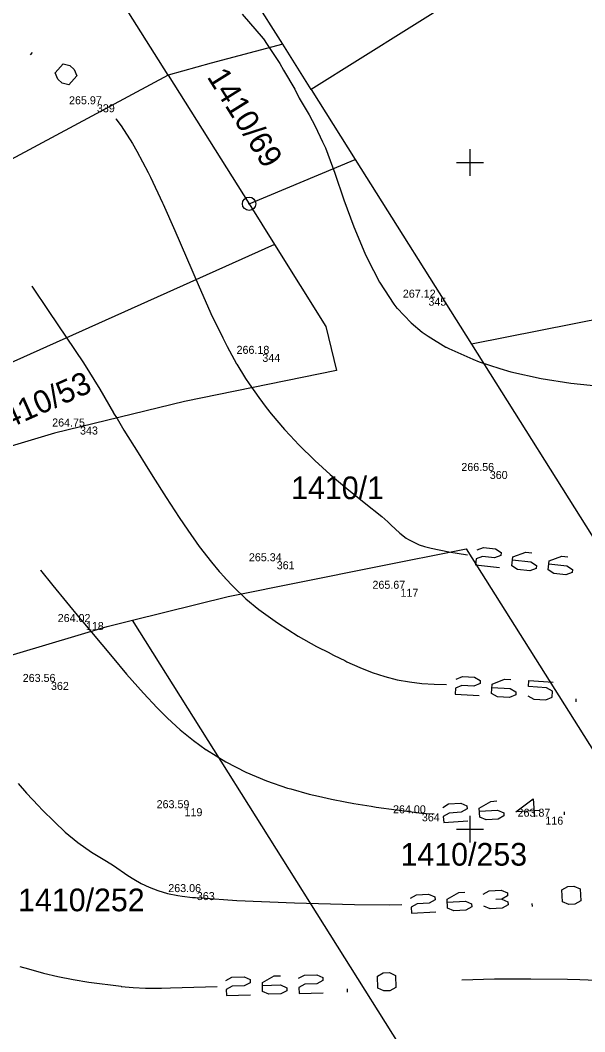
# Model space of a CAD drawing. Extents: x -771260 to -770828, y -1053564 to -1052811.
# Drawn here: x -771133.7 to -771091.4, y -1053315.2 to -1053239.3 of the extents above; entities that cross this region are included whole.
import ezdxf

# ---------------------------------------------------------------- set-up
doc = ezdxf.new("R2010")
doc.units = 0
for name, color, linetype in [('14_8_2023_krizky', 7, 'Continuous'), ('25_3_2019_krizky_JTSK', 7, 'Continuous'), ('25_3_2019_vrstevnice_interval_po_1m', 7, 'Continuous'), ('25_3_2019_zamereny_bod', 7, 'Continuous'), ('25_3_2019_zamereny_bod_cislo', 7, 'Continuous'), ('25_3_2019_zamereny_bod_vyska', 7, 'Continuous'), ('Default', 7, 'Continuous'), ('DKM_Hranice parcel', 7, 'Continuous'), ('DKM_Parcelní čísla', 7, 'Continuous'), ('DKM_Značky bodu BP', 7, 'Continuous')]:
    doc.layers.add(name, color=color, linetype=linetype)

# ---------------------------------------------------------------- blocks, each defined once
blk = doc.blocks.new('POINT_DISPLAY')
at = {"layer": 'Default'}
blk.add_line((0, 0), (0, 0), dxfattribs=at)
blk = doc.blocks.new('KRIZEK')
at = {"layer": '25_3_2019_krizky_JTSK'}
for p, q in [((0, 10), (0, -10)), ((-10, 0), (10, 0))]:
    blk.add_line(p, q, dxfattribs=at)

msp = doc.modelspace()

# ---------------------------------------------------------------- linework, layer by layer
at = {"layer": '25_3_2019_vrstevnice_interval_po_1m'}
for points in [[(-771117.062, -1053238.874), (-771115.486, -1053240.713), (-771115.476, -1053240.728), (-771115.202, -1053241.154), (-771114.241, -1053242.582), (-771113.974, -1053243.076), (-771113.128, -1053244.503), (-771112.786, -1053245.17), (-771112.042, -1053246.435), (-771111.601, -1053247.274), (-771111.043, -1053248.45), (-771110.833, -1053248.912), (-771110.128, -1053250.816), (-771109.441, -1053252.803), (-771108.706, -1053254.837), (-771108.009, -1053256.517), (-771107.828, -1053256.932), (-771107.232, -1053258.116), (-771106.779, -1053258.969), (-771106.417, -1053259.545), (-771105.696, -1053260.633), (-771105.482, -1053260.923), (-771105.468, -1053260.938), (-771104.417, -1053262.017), (-771103.584, -1053262.719), (-771103.128, -1053263.036), (-771101.802, -1053263.855), (-771101.785, -1053263.865), (-771101.586, -1053263.962), (-771099.799, -1053264.752), (-771099.303, -1053264.957), (-771097.772, -1053265.449), (-771096.944, -1053265.702), (-771094.669, -1053266.208), (-771092.454, -1053266.546), (-771090.278, -1053266.772)], [(-771115.486, -1053240.713), (-771115.486, -1053240.713)], [(-771132.92, -1053241.936), (-771132.769, -1053241.767)], [(-771115.202, -1053241.154), (-771115.202, -1053241.154)], [(-771130.888, -1053243.749), (-771131.076, -1053243.278), (-771130.471, -1053242.6), (-771129.982, -1053242.733), (-771129.643, -1053243.035), (-771129.455, -1053243.507), (-771130.06, -1053244.184), (-771130.549, -1053244.051), (-771130.888, -1053243.749)], [(-771114.241, -1053242.582), (-771114.241, -1053242.582)], [(-771113.974, -1053243.076), (-771113.974, -1053243.076)], [(-771113.128, -1053244.503), (-771113.128, -1053244.503)], [(-771112.786, -1053245.17), (-771112.786, -1053245.17)], [(-771126.53, -1053246.725), (-771126.53, -1053246.725)], [(-771126.53, -1053246.725), (-771126.142, -1053247.267), (-771125.29, -1053248.593), (-771124.963, -1053249.162), (-771124.116, -1053250.747), (-771123.933, -1053251.116), (-771123.036, -1053253.033), (-771122.996, -1053253.122), (-771122.104, -1053255.117), (-771120.368, -1053259.156), (-771119.406, -1053261.324), (-771118.528, -1053263.153), (-771118.198, -1053263.802), (-771117.489, -1053265.105), (-771117.48, -1053265.12), (-771116.825, -1053266.205), (-771116.55, -1053266.609), (-771115.825, -1053267.637), (-771115.277, -1053268.378), (-771115.27, -1053268.388), (-771114.893, -1053268.855), (-771113.891, -1053270.031), (-771113.482, -1053270.484), (-771112.819, -1053271.177), (-771111.623, -1053272.355), (-771110.484, -1053273.389), (-771109.231, -1053274.458), (-771107.937, -1053275.51), (-771106.608, -1053276.547), (-771106.593, -1053276.56), (-771106.147, -1053276.951), (-771105.928, -1053277.183), (-771105.269, -1053277.804), (-771104.774, -1053278.168), (-771104.596, -1053278.286), (-771104.161, -1053278.508), (-771103.804, -1053278.67), (-771103.417, -1053278.792), (-771102.92, -1053278.934), (-771102.91, -1053278.936), (-771101.575, -1053279.2), (-771100.189, -1053279.428)], [(-771112.042, -1053246.435), (-771112.042, -1053246.435)], [(-771126.142, -1053247.267), (-771126.142, -1053247.267)], [(-771111.601, -1053247.274), (-771111.601, -1053247.274)], [(-771111.601, -1053247.274), (-771111.601, -1053247.274)], [(-771125.29, -1053248.593), (-771125.29, -1053248.593)], [(-771111.043, -1053248.45), (-771111.043, -1053248.45)], [(-771124.963, -1053249.162), (-771124.963, -1053249.162)], [(-771110.833, -1053248.912), (-771110.833, -1053248.912)], [(-771124.116, -1053250.747), (-771124.116, -1053250.747)], [(-771110.128, -1053250.816), (-771110.128, -1053250.816)], [(-771123.933, -1053251.116), (-771123.933, -1053251.116)], [(-771123.036, -1053253.033), (-771123.036, -1053253.033)], [(-771109.441, -1053252.803), (-771109.441, -1053252.803)], [(-771122.104, -1053255.117), (-771122.104, -1053255.117)], [(-771108.706, -1053254.837), (-771108.706, -1053254.837)], [(-771108.009, -1053256.517), (-771108.009, -1053256.517)], [(-771107.828, -1053256.932), (-771107.828, -1053256.932)], [(-771107.232, -1053258.116), (-771107.232, -1053258.116)], [(-771132.834, -1053259.279), (-771132.834, -1053259.279)], [(-771132.834, -1053259.279), (-771131.551, -1053261.172), (-771128.965, -1053265.015), (-771128.961, -1053265.021), (-771127.727, -1053266.995), (-771126.708, -1053268.783), (-771126.699, -1053268.798), (-771126.443, -1053269.201), (-771125.926, -1053270.068), (-771124.862, -1053271.764), (-771124.33, -1053272.628), (-771123.756, -1053273.544), (-771122.765, -1053275.126), (-771121.788, -1053276.625), (-771121.148, -1053277.571), (-771120.28, -1053278.791), (-771119.372, -1053279.965), (-771118.78, -1053280.67), (-771118.374, -1053281.127), (-771118.359, -1053281.142), (-771117.718, -1053281.826), (-771116.791, -1053282.717), (-771115.83, -1053283.518), (-771115.828, -1053283.52), (-771114.416, -1053284.531), (-771112.864, -1053285.518), (-771111.489, -1053286.295), (-771110.526, -1053286.777), (-771110.501, -1053286.79), (-771110.17, -1053286.971), (-771109.366, -1053287.358), (-771109.218, -1053287.437), (-771108.261, -1053287.873), (-771107.326, -1053288.246), (-771106.389, -1053288.554), (-771105.46, -1053288.786), (-771104.544, -1053288.949), (-771104.537, -1053288.95), (-771103.603, -1053289.062), (-771102.674, -1053289.12), (-771101.749, -1053289.144)], [(-771120.368, -1053259.156), (-771120.368, -1053259.156)], [(-771106.779, -1053258.969), (-771106.779, -1053258.969)], [(-771106.417, -1053259.545), (-771106.417, -1053259.545)], [(-771105.696, -1053260.633), (-771105.696, -1053260.633)], [(-771131.551, -1053261.172), (-771131.551, -1053261.172)], [(-771119.406, -1053261.324), (-771119.406, -1053261.324)], [(-771105.482, -1053260.923), (-771105.482, -1053260.923)], [(-771104.417, -1053262.017), (-771104.417, -1053262.017)], [(-771103.584, -1053262.719), (-771103.584, -1053262.719)], [(-771103.128, -1053263.036), (-771103.128, -1053263.036)], [(-771118.528, -1053263.153), (-771118.528, -1053263.153)], [(-771118.198, -1053263.802), (-771118.198, -1053263.802)], [(-771101.785, -1053263.865), (-771101.785, -1053263.865)], [(-771101.586, -1053263.962), (-771101.586, -1053263.962)], [(-771128.961, -1053265.021), (-771128.961, -1053265.021)], [(-771117.489, -1053265.105), (-771117.489, -1053265.105)], [(-771099.799, -1053264.752), (-771099.799, -1053264.752)], [(-771099.303, -1053264.957), (-771099.303, -1053264.957)], [(-771097.772, -1053265.449), (-771097.772, -1053265.449)], [(-771096.944, -1053265.702), (-771096.944, -1053265.702)], [(-771116.825, -1053266.205), (-771116.825, -1053266.205)], [(-771116.55, -1053266.609), (-771116.55, -1053266.609)], [(-771094.669, -1053266.208), (-771094.669, -1053266.208)], [(-771092.454, -1053266.546), (-771092.454, -1053266.546)], [(-771127.727, -1053266.995), (-771127.727, -1053266.995)], [(-771115.825, -1053267.637), (-771115.825, -1053267.637)], [(-771115.27, -1053268.388), (-771115.27, -1053268.388)], [(-771126.708, -1053268.783), (-771126.708, -1053268.783)], [(-771114.893, -1053268.855), (-771114.893, -1053268.855)], [(-771126.443, -1053269.201), (-771126.443, -1053269.201)], [(-771125.926, -1053270.068), (-771125.926, -1053270.068)], [(-771113.891, -1053270.031), (-771113.891, -1053270.031)], [(-771113.482, -1053270.484), (-771113.482, -1053270.484)], [(-771112.819, -1053271.177), (-771112.819, -1053271.177)], [(-771124.862, -1053271.764), (-771124.862, -1053271.764)], [(-771124.33, -1053272.628), (-771124.33, -1053272.628)], [(-771111.623, -1053272.355), (-771111.623, -1053272.355)], [(-771110.484, -1053273.389), (-771110.484, -1053273.389)], [(-771109.231, -1053274.458), (-771109.231, -1053274.458)], [(-771122.765, -1053275.126), (-771122.765, -1053275.126)], [(-771107.937, -1053275.51), (-771107.937, -1053275.51)], [(-771121.788, -1053276.625), (-771121.788, -1053276.625)], [(-771106.608, -1053276.547), (-771106.608, -1053276.547)], [(-771106.147, -1053276.951), (-771106.147, -1053276.951)], [(-771105.928, -1053277.183), (-771105.928, -1053277.183)], [(-771121.148, -1053277.571), (-771121.148, -1053277.571)], [(-771105.269, -1053277.804), (-771105.269, -1053277.804)], [(-771104.774, -1053278.168), (-771104.774, -1053278.168)], [(-771120.28, -1053278.791), (-771120.28, -1053278.791)], [(-771104.596, -1053278.286), (-771104.596, -1053278.286)], [(-771104.161, -1053278.508), (-771104.161, -1053278.508)], [(-771103.804, -1053278.67), (-771103.804, -1053278.67)], [(-771103.417, -1053278.792), (-771103.417, -1053278.792)], [(-771102.92, -1053278.934), (-771102.92, -1053278.934)], [(-771099.462, -1053279.052), (-771098.986, -1053278.877), (-771098.084, -1053278.978), (-771097.658, -1053279.253), (-771097.683, -1053279.479), (-771098.159, -1053279.654), (-771099.061, -1053279.554), (-771099.538, -1053279.729), (-771099.588, -1053280.18), (-771097.783, -1053280.381)], [(-771101.575, -1053279.2), (-771101.575, -1053279.2)], [(-771096.806, -1053279.805), (-771095.453, -1053279.956), (-771095.027, -1053280.231), (-771095.052, -1053280.457), (-771095.528, -1053280.632), (-771096.43, -1053280.532), (-771096.856, -1053280.256), (-771096.781, -1053279.579), (-771095.828, -1053279.229), (-771095.377, -1053279.279)], [(-771094.099, -1053280.106), (-771092.746, -1053280.257), (-771092.32, -1053280.533), (-771092.345, -1053280.759), (-771092.822, -1053280.934), (-771093.724, -1053280.833), (-771094.15, -1053280.558), (-771094.074, -1053279.881), (-771093.122, -1053279.53), (-771092.671, -1053279.581)], [(-771119.372, -1053279.965), (-771119.372, -1053279.965)], [(-771132.175, -1053280.583), (-771132.175, -1053280.583)], [(-771132.175, -1053280.583), (-771131.256, -1053281.734), (-771129.196, -1053284.225), (-771129.16, -1053284.267), (-771128.865, -1053284.617), (-771128.404, -1053285.164), (-771128.36, -1053285.217), (-771126.812, -1053287.08), (-771125.728, -1053288.366), (-771124.471, -1053289.799), (-771123.438, -1053290.898), (-771122.653, -1053291.679), (-771121.713, -1053292.536), (-771120.716, -1053293.345), (-771119.754, -1053294.036), (-771119.751, -1053294.037), (-771118.297, -1053294.933), (-771116.794, -1053295.711), (-771115.247, -1053296.368), (-771113.66, -1053296.918), (-771113.419, -1053296.98), (-771112.038, -1053297.374), (-771111.352, -1053297.52), (-771110.387, -1053297.753), (-771109.357, -1053297.936), (-771108.713, -1053298.07), (-771107.41, -1053298.268), (-771107.021, -1053298.34), (-771105.494, -1053298.546), (-771105.317, -1053298.576), (-771103.616, -1053298.789), (-771103.608, -1053298.79), (-771103.605, -1053298.79), (-771103.281, -1053298.813), (-771102.693, -1053298.854)], [(-771118.78, -1053280.67), (-771118.78, -1053280.67)], [(-771118.374, -1053281.127), (-771118.374, -1053281.127)], [(-771131.256, -1053281.734), (-771131.256, -1053281.734)], [(-771117.718, -1053281.826), (-771117.718, -1053281.826)], [(-771116.791, -1053282.717), (-771116.791, -1053282.717)], [(-771115.83, -1053283.518), (-771115.83, -1053283.518)], [(-771129.196, -1053284.225), (-771129.196, -1053284.225)], [(-771114.416, -1053284.531), (-771114.416, -1053284.531)], [(-771128.36, -1053285.217), (-771128.36, -1053285.217)], [(-771112.864, -1053285.518), (-771112.864, -1053285.518)], [(-771111.489, -1053286.295), (-771111.489, -1053286.295)], [(-771126.812, -1053287.08), (-771126.812, -1053287.08)], [(-771110.501, -1053286.79), (-771110.501, -1053286.79)], [(-771110.17, -1053286.971), (-771110.17, -1053286.971)], [(-771109.366, -1053287.358), (-771109.366, -1053287.358)], [(-771109.218, -1053287.437), (-771109.218, -1053287.437)], [(-771108.261, -1053287.873), (-771108.261, -1053287.873)], [(-771125.728, -1053288.366), (-771125.728, -1053288.366)], [(-771107.326, -1053288.246), (-771107.326, -1053288.246)], [(-771106.389, -1053288.554), (-771106.389, -1053288.554)], [(-771105.46, -1053288.786), (-771105.46, -1053288.786)], [(-771101.041, -1053288.735), (-771100.573, -1053288.537), (-771099.667, -1053288.594), (-771099.229, -1053288.849), (-771099.243, -1053289.076), (-771099.71, -1053289.274), (-771100.616, -1053289.216), (-771101.084, -1053289.414), (-771101.112, -1053289.867), (-771099.301, -1053289.982)], [(-771098.352, -1053289.36), (-771096.993, -1053289.446), (-771096.554, -1053289.701), (-771096.568, -1053289.928), (-771097.036, -1053290.125), (-771097.942, -1053290.068), (-771098.38, -1053289.813), (-771098.337, -1053289.133), (-771097.403, -1053288.738), (-771096.95, -1053288.766)], [(-771095.663, -1053289.985), (-771095.224, -1053290.24), (-771094.318, -1053290.298), (-771093.851, -1053290.1), (-771093.822, -1053289.647), (-771094.261, -1053289.392), (-771095.62, -1053289.305), (-771095.591, -1053288.853), (-771093.779, -1053288.967)], [(-771104.537, -1053288.95), (-771104.537, -1053288.95)], [(-771103.603, -1053289.062), (-771103.603, -1053289.062)], [(-771102.674, -1053289.12), (-771102.674, -1053289.12)], [(-771124.471, -1053289.799), (-771124.471, -1053289.799)], [(-771092.053, -1053290.441), (-771092.039, -1053290.215)], [(-771123.438, -1053290.898), (-771123.438, -1053290.898)], [(-771122.653, -1053291.679), (-771122.653, -1053291.679)], [(-771121.713, -1053292.536), (-771121.713, -1053292.536)], [(-771120.716, -1053293.345), (-771120.716, -1053293.345)], [(-771119.754, -1053294.036), (-771119.754, -1053294.036)], [(-771118.297, -1053294.933), (-771118.297, -1053294.933)], [(-771116.794, -1053295.711), (-771116.794, -1053295.711)], [(-771115.247, -1053296.368), (-771115.247, -1053296.368)], [(-771133.861, -1053296.577), (-771133.233, -1053297.289), (-771132.324, -1053298.256), (-771132.05, -1053298.548), (-771131.134, -1053299.455), (-771130.32, -1053300.208), (-771129.377, -1053300.985), (-771128.36, -1053301.712), (-771127.244, -1053302.39), (-771126.72, -1053302.709), (-771125.622, -1053303.474), (-771125.195, -1053303.75), (-771124.641, -1053304.066), (-771124.045, -1053304.355), (-771123.389, -1053304.601), (-771122.675, -1053304.809), (-771121.893, -1053304.971), (-771121.567, -1053305.011), (-771120.792, -1053305.106), (-771120.781, -1053305.107), (-771120.576, -1053305.121), (-771120.138, -1053305.151), (-771117.457, -1053305.334), (-771113.147, -1053305.52), (-771108.651, -1053305.64), (-771106.042, -1053305.667), (-771106.039, -1053305.667), (-771105.101, -1053305.649)], [(-771113.66, -1053296.918), (-771113.66, -1053296.918)], [(-771113.419, -1053296.98), (-771113.419, -1053296.98)], [(-771133.233, -1053297.289), (-771133.233, -1053297.289)], [(-771112.038, -1053297.374), (-771112.038, -1053297.374)], [(-771111.352, -1053297.52), (-771111.352, -1053297.52)], [(-771110.387, -1053297.753), (-771110.387, -1053297.753)], [(-771109.357, -1053297.936), (-771109.357, -1053297.936)], [(-771099.295, -1053298.644), (-771097.936, -1053298.56), (-771097.469, -1053298.758), (-771097.455, -1053298.984), (-771097.894, -1053299.239), (-771098.8, -1053299.295), (-771099.267, -1053299.097), (-771099.309, -1053298.417), (-771098.431, -1053297.908), (-771097.978, -1053297.88)], [(-771094.751, -1053298.59), (-771096.563, -1053298.702), (-771095.26, -1053297.712), (-771095.176, -1053299.071)], [(-771132.05, -1053298.548), (-771132.05, -1053298.548)], [(-771108.713, -1053298.07), (-771108.713, -1053298.07)], [(-771107.41, -1053298.268), (-771107.41, -1053298.268)], [(-771107.021, -1053298.34), (-771107.021, -1053298.34)], [(-771105.494, -1053298.546), (-771105.494, -1053298.546)], [(-771105.317, -1053298.576), (-771105.317, -1053298.576)], [(-771102.041, -1053298.359), (-771101.602, -1053298.104), (-771100.696, -1053298.048), (-771100.229, -1053298.247), (-771100.215, -1053298.473), (-771100.654, -1053298.728), (-771101.56, -1053298.784), (-771101.999, -1053299.038), (-771101.971, -1053299.491), (-771100.159, -1053299.379)], [(-771092.911, -1053298.93), (-771092.925, -1053298.704)], [(-771131.134, -1053299.455), (-771131.134, -1053299.455)], [(-771103.605, -1053298.79), (-771103.605, -1053298.79)], [(-771130.32, -1053300.208), (-771130.32, -1053300.208)], [(-771129.377, -1053300.985), (-771129.377, -1053300.985)], [(-771128.36, -1053301.712), (-771128.36, -1053301.712)], [(-771126.72, -1053302.709), (-771126.72, -1053302.709)], [(-771125.622, -1053303.474), (-771125.622, -1053303.474)], [(-771125.195, -1053303.75), (-771125.195, -1053303.75)], [(-771124.641, -1053304.066), (-771124.641, -1053304.066)], [(-771124.045, -1053304.355), (-771124.045, -1053304.355)], [(-771123.389, -1053304.601), (-771123.389, -1053304.601)], [(-771122.675, -1053304.809), (-771122.675, -1053304.809)], [(-771101.702, -1053305.464), (-771100.342, -1053305.391), (-771099.877, -1053305.593), (-771099.865, -1053305.819), (-771100.306, -1053306.071), (-771101.212, -1053306.12), (-771101.678, -1053305.918), (-771101.714, -1053305.238), (-771100.833, -1053304.735), (-771100.379, -1053304.711)], [(-771099.007, -1053304.864), (-771098.567, -1053304.613), (-771097.66, -1053304.564), (-771097.195, -1053304.766), (-771097.182, -1053304.992), (-771097.623, -1053305.243)], [(-771092.601, -1053305.653), (-771093.067, -1053305.451), (-771093.116, -1053304.545), (-771092.675, -1053304.293), (-771092.222, -1053304.269), (-771091.756, -1053304.471), (-771091.707, -1053305.377), (-771092.148, -1053305.628), (-771092.601, -1053305.653)], [(-771121.893, -1053304.971), (-771121.893, -1053304.971)], [(-771120.792, -1053305.106), (-771120.792, -1053305.106)], [(-771117.457, -1053305.334), (-771117.457, -1053305.334)], [(-771113.147, -1053305.52), (-771113.147, -1053305.52)], [(-771104.446, -1053305.159), (-771104.005, -1053304.907), (-771103.099, -1053304.858), (-771102.633, -1053305.06), (-771102.621, -1053305.287), (-771103.062, -1053305.538), (-771103.968, -1053305.587), (-771104.409, -1053305.838), (-771104.384, -1053306.292), (-771102.572, -1053306.193)], [(-771097.623, -1053305.243), (-771097.158, -1053305.445), (-771097.145, -1053305.672), (-771097.586, -1053305.923), (-771098.493, -1053305.972), (-771098.958, -1053305.77)], [(-771097.623, -1053305.243), (-771098.076, -1053305.268)], [(-771095.32, -1053305.8), (-771095.333, -1053305.574)], [(-771108.651, -1053305.64), (-771108.651, -1053305.64)], [(-771106.042, -1053305.667), (-771106.042, -1053305.667)], [(-771133.721, -1053310.279), (-771133.087, -1053310.474), (-771131.944, -1053310.794), (-771130.883, -1053311.046), (-771129.735, -1053311.274), (-771128.557, -1053311.466), (-771126.145, -1053311.778), (-771126.133, -1053311.779), (-771125.243, -1053311.871), (-771124.301, -1053311.914), (-771123.116, -1053311.908), (-771122.439, -1053311.891), (-771118.95, -1053311.803)], [(-771133.087, -1053310.474), (-771133.087, -1053310.474)], [(-771131.944, -1053310.794), (-771131.944, -1053310.794)], [(-771106.454, -1053312.127), (-771106.914, -1053311.913), (-771106.94, -1053311.006), (-771106.493, -1053310.766), (-771106.039, -1053310.753), (-771105.579, -1053310.967), (-771105.553, -1053311.874), (-771106, -1053312.114), (-771106.454, -1053312.127)], [(-771130.883, -1053311.046), (-771130.883, -1053311.046)], [(-771129.735, -1053311.274), (-771129.735, -1053311.274)], [(-771128.557, -1053311.466), (-771128.557, -1053311.466)], [(-771118.282, -1053311.33), (-771117.835, -1053311.09), (-771116.927, -1053311.064), (-771116.467, -1053311.278), (-771116.461, -1053311.505), (-771116.908, -1053311.744), (-771117.815, -1053311.77), (-771118.263, -1053312.01), (-771118.25, -1053312.464), (-771116.435, -1053312.412)], [(-771115.547, -1053311.706), (-771114.186, -1053311.667), (-771113.726, -1053311.881), (-771113.719, -1053312.107), (-771114.166, -1053312.347), (-771115.074, -1053312.373), (-771115.534, -1053312.159), (-771115.553, -1053311.479), (-771114.659, -1053310.999), (-771114.205, -1053310.986)], [(-771112.838, -1053311.174), (-771112.391, -1053310.934), (-771111.483, -1053310.908), (-771111.023, -1053311.122), (-771111.017, -1053311.349), (-771111.464, -1053311.589), (-771112.371, -1053311.615), (-771112.818, -1053311.855), (-771112.805, -1053312.308), (-771110.991, -1053312.257)], [(-771100.606, -1053311.279), (-771098.156, -1053311.225), (-771095.444, -1053311.208), (-771092.707, -1053311.234), (-771091.759, -1053311.258), (-771089.927, -1053311.333), (-771088.515, -1053311.406), (-771087.126, -1053311.498), (-771087.108, -1053311.5), (-771086.439, -1053311.524), (-771085.993, -1053311.558), (-771085.494, -1053311.596), (-771085.492, -1053311.596), (-771084.974, -1053311.67), (-771084.079, -1053311.811), (-771082.816, -1053312.053)], [(-771100.606, -1053311.279), (-771100.606, -1053311.279)], [(-771098.156, -1053311.225), (-771098.156, -1053311.225)], [(-771095.444, -1053311.208), (-771095.444, -1053311.208)], [(-771092.707, -1053311.234), (-771092.707, -1053311.234)], [(-771091.759, -1053311.258), (-771091.759, -1053311.258)], [(-771126.145, -1053311.778), (-771126.145, -1053311.778)], [(-771125.243, -1053311.871), (-771125.243, -1053311.871)], [(-771124.301, -1053311.914), (-771124.301, -1053311.914)], [(-771123.116, -1053311.908), (-771123.116, -1053311.908)], [(-771109.176, -1053312.205), (-771109.182, -1053311.978)]]:
    msp.add_lwpolyline(points, dxfattribs=at)
at = {"layer": 'DKM_Hranice parcel'}
for p, q in [((-771074.04, -1053220.76), (-771111.89, -1053244.54)), ((-771122.61, -1053243.46), (-771134.3, -1053224.85)), ((-771114.03, -1053241.13), (-771123.59, -1053225.92)), ((-771111.89, -1053244.54), (-771114.03, -1053241.13)), ((-771122.61, -1053243.46), (-771166.82, -1053267.21)), ((-771122.61, -1053243.46), (-771116.55, -1053253.1)), ((-771111.89, -1053244.54), (-771108.61, -1053249.77)), ((-771116.55, -1053253.1), (-771108.61, -1053249.77)), ((-771108.61, -1053249.77), (-771099.9, -1053263.62)), ((-771116.55, -1053253.1), (-771114.64, -1053256.15)), ((-771114.64, -1053256.15), (-771161.21, -1053277.05)), ((-771065.57, -1053256.8), (-771099.9, -1053263.62)), ((-771099.9, -1053263.62), (-771089.93, -1053279.48)), ((-771104.14, -1053317.95), (-771125.28, -1053284.32))]:
    msp.add_line(p, q, dxfattribs=at)
for points in [[(-771114.03, -1053241.13), (-771119.4, -1053242.55), (-771122.61, -1053243.46)], [(-771114.64, -1053256.15), (-771110.79, -1053262.31), (-771110, -1053265.61), (-771121.4, -1053267.92), (-771131.13, -1053270.31), (-771140.72, -1053273.18), (-771150.13, -1053276.39), (-771159.39, -1053280.23)], [(-771125.28, -1053284.32), (-771118.12, -1053282.56), (-771107.06, -1053280.32), (-771100.29, -1053278.98), (-771077.89, -1053314.54)], [(-771151.89, -1053293.35), (-771144.83, -1053290.43), (-771136.15, -1053287.47), (-771127.19, -1053284.79), (-771125.28, -1053284.32)]]:
    msp.add_lwpolyline(points, dxfattribs=at)
at = {"layer": 'DKM_Značky bodu BP'}
for radius in [0.5, 0.0303]:
    msp.add_circle((-771116.55, -1053253.1), radius, dxfattribs=at)

# ---------------------------------------------------------------- block references
at = {"layer": '14_8_2023_krizky', "xscale": 0.1, "yscale": 0.10000000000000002}
for p in [(-771100, -1053250), (-771100, -1053300)]:
    msp.add_blockref('KRIZEK', p, dxfattribs=at)
at = {"layer": '25_3_2019_zamereny_bod', "xscale": 0.1, "yscale": 0.10000000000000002}
for p in [(-771127.952, -1053245.64), (-771103.115, -1053260.141), (-771115.556, -1053264.353), (-771129.215, -1053269.802), (-771098.519, -1053273.136), (-771114.479, -1053279.905), (-771105.207, -1053281.97), (-771128.775, -1053284.463), (-771131.394, -1053288.954), (-771121.387, -1053298.421), (-771103.607, -1053298.804), (-771094.352, -1053299.058), (-771120.464, -1053304.712)]:
    msp.add_blockref('POINT_DISPLAY', p, dxfattribs=at)

# ---------------------------------------------------------------- texts
at = {"layer": '25_3_2019_zamereny_bod_cislo'}
for s, p in [('339', (-771127.952, -1053246.24)), ('345', (-771103.115, -1053260.741)), ('344', (-771115.556, -1053264.953)), ('343', (-771129.215, -1053270.402)), ('360', (-771098.519, -1053273.736)), ('361', (-771114.479, -1053280.505)), ('117', (-771105.207, -1053282.57)), ('118', (-771128.775, -1053285.063)), ('362', (-771131.394, -1053289.554)), ('119', (-771121.387, -1053299.021)), ('364', (-771103.607, -1053299.404)), ('116', (-771094.352, -1053299.658)), ('363', (-771120.464, -1053305.312))]:
    msp.add_text(s, height=0.6, dxfattribs=at).set_placement(p)
at = {"layer": '25_3_2019_zamereny_bod_vyska'}
for s, p in [('265.97 ', (-771130.039, -1053245.64)), ('267.12 ', (-771105.03, -1053260.141)), ('266.18 ', (-771117.488, -1053264.353)), ('264.75 ', (-771131.301, -1053269.802)), ('266.56 ', (-771100.649, -1053273.136)), ('265.34 ', (-771116.565, -1053279.905)), ('265.67 ', (-771107.308, -1053281.97)), ('264.02 ', (-771130.887, -1053284.463)), ('263.56 ', (-771133.508, -1053288.954)), ('263.59 ', (-771123.477, -1053298.421)), ('264.00 ', (-771105.766, -1053298.804)), ('263.87 ', (-771096.436, -1053299.058)), ('263.06 ', (-771122.604, -1053304.712))]:
    msp.add_text(s, height=0.6, dxfattribs=at).set_placement(p)
at = {"layer": 'DKM_Parcelní čísla'}
for s, rotation, p in [('1410/69', 302, (-771119.746, -1053243.582)), ('1410/53', 24, (-771135.724, -1053270.496))]:
    msp.add_text(s, height=1.7, rotation=rotation, dxfattribs=at).set_placement(p)
for s, p in [('1410/1', (-771113.4, -1053275.249)), ('1410/253', (-771105.205, -1053302.729)), ('1410/252', (-771133.855, -1053306.15))]:
    msp.add_text(s, height=1.7, dxfattribs=at).set_placement(p)

doc.saveas('drawing.dxf')
